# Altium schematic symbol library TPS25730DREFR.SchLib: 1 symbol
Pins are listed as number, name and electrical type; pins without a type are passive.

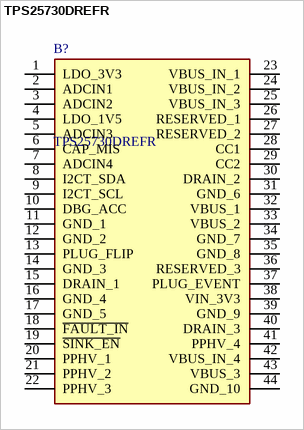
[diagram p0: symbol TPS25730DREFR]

## TPS25730DREFR
designator B?
USB Interface IC TPS25730DREFR SARUMAN BG MCM; Manufacturer_Name: Texas Instruments; Geometry.Height: 0.8mm
footprint TPS25730DREFR
pins: 1 LDO_3V3, 2 ADCIN1, 3 ADCIN2, 4 LDO_1V5, 5 ADCIN3, 6 CAP_MIS, 7 ADCIN4, 8 I2CT_SDA, 9 I2CT_SCL, 10 DBG_ACC, 11 GND_1, 12 GND_2, 13 PLUG_FLIP, 14 GND_3, 15 DRAIN_1, 16 GND_4, 17 GND_5, 18 ~{FAULT_IN}, 19 ~{SINK_EN}, 20 PPHV_1, 21 PPHV_2, 22 PPHV_3, 23 VBUS_IN_1, 24 VBUS_IN_2, 25 VBUS_IN_3, 26 RESERVED_1, 27 RESERVED_2, 28 CC1, 29 CC2, 30 DRAIN_2, 31 GND_6, 32 VBUS_1, 33 VBUS_2, 34 GND_7, 35 GND_8, 36 RESERVED_3, 37 PLUG_EVENT, 38 VIN_3V3, 39 GND_9, 40 DRAIN_3, 41 PPHV_4, 42 VBUS_IN_4, 43 VBUS_3, 44 GND_10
